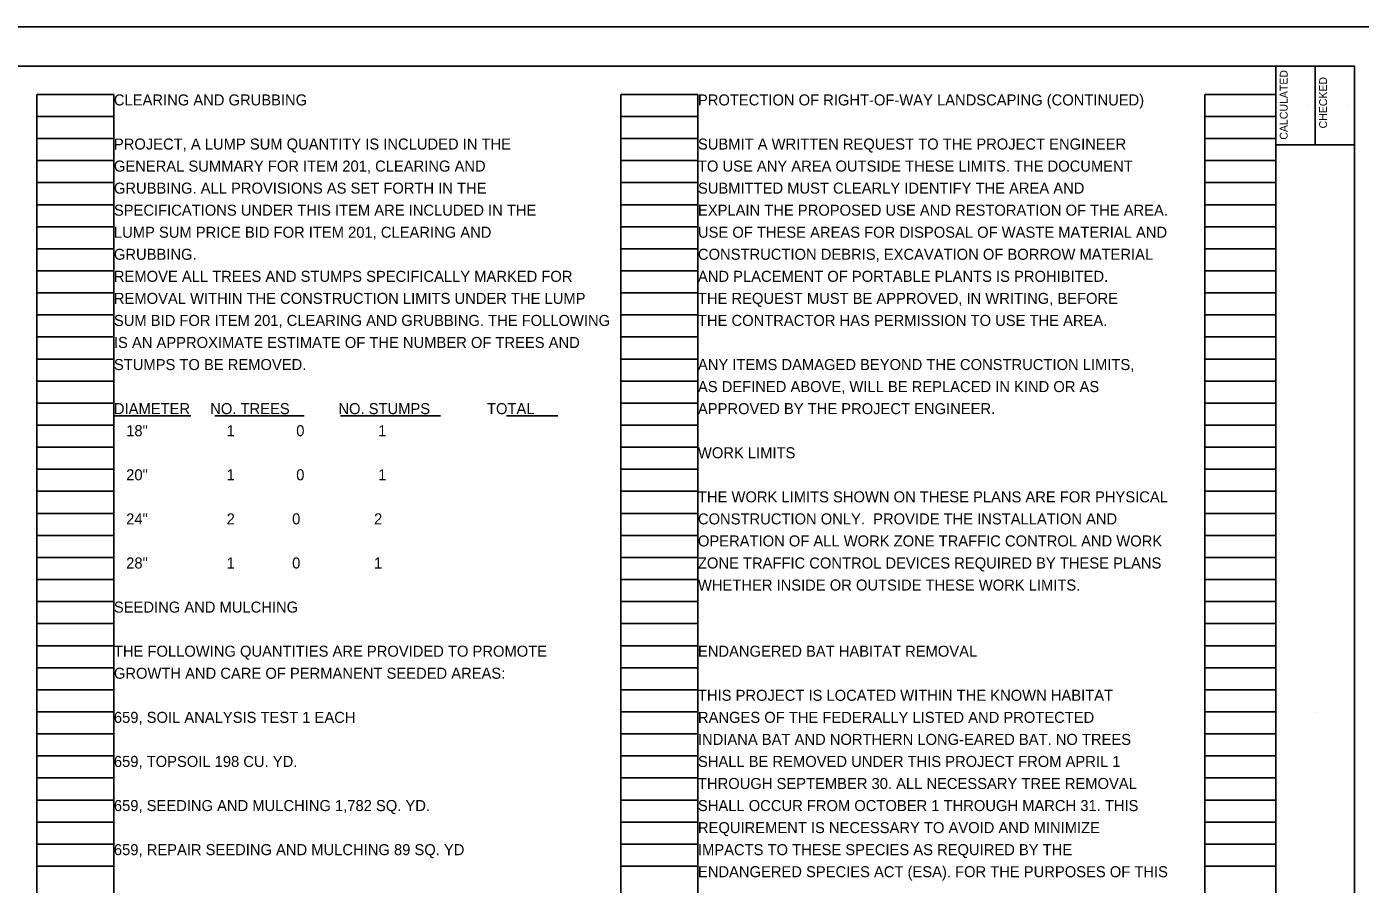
# Model space of a CAD drawing. Extents: x 0 to 50.5, y 0 to 22.
# Drawn here: x 16.63 to 33.58, y 11.11 to 22 of the extents above; entities that cross this region are included whole.
import ezdxf

# ---------------------------------------------------------------- set-up
doc = ezdxf.new("R2010")
doc.units = 0
for name, color, linetype in [('SC_Scratch1', 7, 'Continuous'), ('SH_Border', 7, 'Continuous'), ('SH_Cut_Line', 7, 'Continuous'), ('SH_Data', 7, 'Continuous'), ('SH_Text', 7, 'Continuous')]:
    doc.layers.add(name, color=color, linetype=linetype)

msp = doc.modelspace()

# ---------------------------------------------------------------- linework, layer by layer
at = {"layer": 'SC_Scratch1'}
for p, q in [((16.76, 0.98), (16.76, 21.14)), ((16.76, 21.14), (17.74, 21.14)), ((17.74, 0.98), (17.74, 21.14)), ((24.18, 0.98), (24.18, 21.14)), ((24.18, 21.14), (25.16, 21.14)), ((25.16, 0.98), (25.16, 21.14)), ((31.6, 0.98), (31.6, 21.14)), ((31.6, 21.14), (32.5, 21.14)), ((32.5, 0.98), (32.5, 21.14)), ((16.76, 20.86), (17.74, 20.86)), ((24.18, 20.86), (25.16, 20.86)), ((31.6, 20.86), (32.5, 20.86)), ((16.76, 20.58), (17.74, 20.58)), ((24.18, 20.58), (25.16, 20.58)), ((31.6, 20.58), (32.5, 20.58)), ((16.76, 20.3), (17.74, 20.3)), ((24.18, 20.3), (25.16, 20.3)), ((31.6, 20.3), (32.5, 20.3)), ((16.76, 20.02), (17.74, 20.02)), ((24.18, 20.02), (25.16, 20.02)), ((31.6, 20.02), (32.5, 20.02)), ((16.76, 19.74), (17.74, 19.74)), ((24.18, 19.74), (25.16, 19.74)), ((31.6, 19.74), (32.5, 19.74)), ((16.76, 19.46), (17.74, 19.46)), ((24.18, 19.46), (25.16, 19.46)), ((31.6, 19.46), (32.5, 19.46)), ((16.76, 19.18), (17.74, 19.18)), ((24.18, 19.18), (25.16, 19.18)), ((31.6, 19.18), (32.5, 19.18)), ((16.76, 18.9), (17.74, 18.9)), ((24.18, 18.9), (25.16, 18.9)), ((31.6, 18.9), (32.5, 18.9)), ((16.76, 18.62), (17.74, 18.62)), ((24.18, 18.62), (25.16, 18.62)), ((31.6, 18.62), (32.5, 18.62)), ((16.76, 18.34), (17.74, 18.34)), ((24.18, 18.34), (25.16, 18.34)), ((31.6, 18.34), (32.5, 18.34)), ((16.76, 18.06), (17.74, 18.06)), ((24.18, 18.06), (25.16, 18.06)), ((31.6, 18.06), (32.5, 18.06)), ((16.76, 17.78), (17.74, 17.78)), ((24.18, 17.78), (25.16, 17.78)), ((31.6, 17.78), (32.5, 17.78)), ((16.76, 17.5), (17.74, 17.5)), ((24.18, 17.5), (25.16, 17.5)), ((31.6, 17.5), (32.5, 17.5)), ((16.76, 17.22), (17.74, 17.22)), ((24.18, 17.22), (25.16, 17.22)), ((31.6, 17.22), (32.5, 17.22)), ((16.76, 16.94), (17.74, 16.94)), ((24.18, 16.94), (25.16, 16.94)), ((31.6, 16.94), (32.5, 16.94)), ((16.76, 16.66), (17.74, 16.66)), ((24.18, 16.66), (25.16, 16.66)), ((31.6, 16.66), (32.5, 16.66)), ((16.76, 16.38), (17.74, 16.38)), ((24.18, 16.38), (25.16, 16.38)), ((31.6, 16.38), (32.5, 16.38)), ((16.76, 16.1), (17.74, 16.1)), ((24.18, 16.1), (25.16, 16.1)), ((31.6, 16.1), (32.5, 16.1)), ((16.76, 15.82), (17.74, 15.82)), ((24.18, 15.82), (25.16, 15.82)), ((31.6, 15.82), (32.5, 15.82)), ((16.76, 15.54), (17.74, 15.54)), ((24.18, 15.54), (25.16, 15.54)), ((31.6, 15.54), (32.5, 15.54)), ((16.76, 15.26), (17.74, 15.26)), ((24.18, 15.26), (25.16, 15.26)), ((31.6, 15.26), (32.5, 15.26)), ((16.76, 14.98), (17.74, 14.98)), ((24.18, 14.98), (25.16, 14.98)), ((31.6, 14.98), (32.5, 14.98)), ((16.76, 14.7), (17.74, 14.7)), ((24.18, 14.7), (25.16, 14.7)), ((31.6, 14.7), (32.5, 14.7)), ((16.76, 14.42), (17.74, 14.42)), ((24.18, 14.42), (25.16, 14.42)), ((31.6, 14.42), (32.5, 14.42)), ((16.76, 14.14), (17.74, 14.14)), ((24.18, 14.14), (25.16, 14.14)), ((31.6, 14.14), (32.5, 14.14)), ((16.76, 13.86), (17.74, 13.86)), ((24.18, 13.86), (25.16, 13.86)), ((31.6, 13.86), (32.5, 13.86)), ((16.76, 13.58), (17.74, 13.58)), ((24.18, 13.58), (25.16, 13.58)), ((31.6, 13.58), (32.5, 13.58)), ((16.76, 13.3), (17.74, 13.3)), ((24.18, 13.3), (25.16, 13.3)), ((31.6, 13.3), (32.5, 13.3)), ((16.76, 13.02), (17.74, 13.02)), ((24.18, 13.02), (25.16, 13.02)), ((31.6, 13.02), (32.5, 13.02)), ((16.76, 12.74), (17.74, 12.74)), ((24.18, 12.74), (25.16, 12.74)), ((31.6, 12.74), (32.5, 12.74)), ((16.76, 12.46), (17.74, 12.46)), ((24.18, 12.46), (25.16, 12.46)), ((31.6, 12.46), (32.5, 12.46)), ((16.76, 12.18), (17.74, 12.18)), ((24.18, 12.18), (25.16, 12.18)), ((31.6, 12.18), (32.5, 12.18)), ((16.76, 11.9), (17.74, 11.9)), ((24.18, 11.9), (25.16, 11.9)), ((31.6, 11.9), (32.5, 11.9)), ((16.76, 11.62), (17.74, 11.62)), ((24.18, 11.62), (25.16, 11.62)), ((31.6, 11.62), (32.5, 11.62)), ((16.76, 11.34), (17.74, 11.34)), ((24.18, 11.34), (25.16, 11.34)), ((31.6, 11.34), (32.5, 11.34))]:
    msp.add_line(p, q, dxfattribs=at)
at = {"layer": 'SH_Border'}
for p, q in [((32.5, 0.5), (32.5, 21.5)), ((33, 21.5), (33, 20.5)), ((32.5, 20.5), (33.5, 20.5))]:
    msp.add_line(p, q, dxfattribs=at)
msp.add_lwpolyline([(2, 21.5), (33.5, 21.5), (33.5, 0.5), (2, 0.5)], close=True, dxfattribs=at)
at = {"layer": 'SH_Cut_Line'}
msp.add_lwpolyline([(0, 0), (34, 0), (34, 22), (0, 22)], close=True, dxfattribs=at)
at = {"layer": 'SH_Data'}
for p, q in [((32.92, 21.004), (32.92, 21.004)), ((33.42, 21.004), (33.42, 21.004)), ((33, 13.292), (33, 13.292))]:
    msp.add_line(p, q, dxfattribs=at)
at = {"layer": 'SH_Text'}
for p, q in [((17.737, 17.059), (18.717, 17.059)), ((19.023, 17.059), (20.158, 17.059)), ((20.617, 17.059), (21.888, 17.059)), ((22.727, 17.059), (23.38, 17.059))]:
    msp.add_line(p, q, dxfattribs=at)

# ---------------------------------------------------------------- texts
at = {"layer": 'SH_Data'}
for s, p in [('CALCULATED', (32.652, 20.565)), ('CHECKED', (33.152, 20.708))]:
    msp.add_text(s, height=0.1, rotation=90, dxfattribs=at).set_placement(p)
at = {"layer": 'SH_Text'}
for s, p in [('CLEARING AND GRUBBING', (17.74, 21)), ('PROTECTION OF RIGHT-OF-WAY LANDSCAPING (CONTINUED)', (25.16, 21)), ('PROJECT, A LUMP SUM QUANTITY IS INCLUDED IN THE', (17.74, 20.44)), ('SUBMIT A WRITTEN REQUEST TO THE PROJECT ENGINEER', (25.16, 20.44)), ('GENERAL SUMMARY FOR ITEM 201, CLEARING AND', (17.74, 20.16)), ('TO USE ANY AREA OUTSIDE THESE LIMITS. THE DOCUMENT', (25.16, 20.16)), ('GRUBBING. ALL PROVISIONS AS SET FORTH IN THE', (17.74, 19.88)), ('SUBMITTED MUST CLEARLY IDENTIFY THE AREA AND', (25.16, 19.88)), ('SPECIFICATIONS UNDER THIS ITEM ARE INCLUDED IN THE', (17.74, 19.6)), ('EXPLAIN THE PROPOSED USE AND RESTORATION OF THE AREA.', (25.16, 19.6)), ('LUMP SUM PRICE BID FOR ITEM 201, CLEARING AND', (17.74, 19.32)), ('USE OF THESE AREAS FOR DISPOSAL OF WASTE MATERIAL AND', (25.16, 19.32)), ('GRUBBING.', (17.74, 19.04)), ('CONSTRUCTION DEBRIS, EXCAVATION OF BORROW MATERIAL', (25.16, 19.04)), ('REMOVE ALL TREES AND STUMPS SPECIFICALLY MARKED FOR', (17.74, 18.76)), ('AND PLACEMENT OF PORTABLE PLANTS IS PROHIBITED.', (25.16, 18.76)), ('REMOVAL WITHIN THE CONSTRUCTION LIMITS UNDER THE LUMP', (17.74, 18.48)), ('THE REQUEST MUST BE APPROVED, IN WRITING, BEFORE', (25.16, 18.48)), ('SUM BID FOR ITEM 201, CLEARING AND GRUBBING. THE FOLLOWING', (17.74, 18.2)), ('THE CONTRACTOR HAS PERMISSION TO USE THE AREA.', (25.16, 18.2)), ('IS AN APPROXIMATE ESTIMATE OF THE NUMBER OF TREES AND', (17.74, 17.92)), ('STUMPS TO BE REMOVED.', (17.74, 17.64)), ('ANY ITEMS DAMAGED BEYOND THE CONSTRUCTION LIMITS,', (25.16, 17.64)), ('AS DEFINED ABOVE, WILL BE REPLACED IN KIND OR AS', (25.16, 17.36)), ('DIAMETER ', (17.74, 17.08)), ('  NO. TREES', (18.86, 17.08)), (' NO. STUMPS', (20.54, 17.08)), ('     TOTAL', (22.22, 17.08)), ('APPROVED BY THE PROJECT ENGINEER.', (25.16, 17.08)), ('   18"   ', (17.74, 16.8)), ('      1               0                  1', (18.86, 16.8)), ('WORK LIMITS', (25.16, 16.52)), ('   20"   ', (17.74, 16.24)), ('      1               0                  1', (18.86, 16.24)), ('THE WORK LIMITS SHOWN ON THESE PLANS ARE FOR PHYSICAL', (25.16, 15.96)), ('   24"   ', (17.74, 15.68)), ('      2              0                  2', (18.86, 15.68)), ('CONSTRUCTION ONLY.  PROVIDE THE INSTALLATION AND', (25.16, 15.68)), ('OPERATION OF ALL WORK ZONE TRAFFIC CONTROL AND WORK', (25.16, 15.4)), ('   28"   ', (17.74, 15.12)), ('      1              0                  1', (18.86, 15.12)), ('ZONE TRAFFIC CONTROL DEVICES REQUIRED BY THESE PLANS', (25.16, 15.12)), ('WHETHER INSIDE OR OUTSIDE THESE WORK LIMITS.', (25.16, 14.84)), ('SEEDING AND MULCHING', (17.74, 14.56)), ('THE FOLLOWING QUANTITIES ARE PROVIDED TO PROMOTE', (17.74, 14)), ('ENDANGERED BAT HABITAT REMOVAL', (25.16, 14)), ('GROWTH AND CARE OF PERMANENT SEEDED AREAS:', (17.74, 13.72)), ('THIS PROJECT IS LOCATED WITHIN THE KNOWN HABITAT', (25.16, 13.44)), ('659, SOIL ANALYSIS TEST 1 EACH', (17.74, 13.16)), ('RANGES OF THE FEDERALLY LISTED AND PROTECTED', (25.16, 13.16)), ('INDIANA BAT AND NORTHERN LONG-EARED BAT. NO TREES', (25.16, 12.88)), ('659, TOPSOIL 198 CU. YD.', (17.74, 12.6)), ('SHALL BE REMOVED UNDER THIS PROJECT FROM APRIL 1', (25.16, 12.6)), ('THROUGH SEPTEMBER 30. ALL NECESSARY TREE REMOVAL', (25.16, 12.32)), ('659, SEEDING AND MULCHING 1,782 SQ. YD.', (17.74, 12.04)), ('SHALL OCCUR FROM OCTOBER 1 THROUGH MARCH 31. THIS', (25.16, 12.04)), ('REQUIREMENT IS NECESSARY TO AVOID AND MINIMIZE', (25.16, 11.76)), ('659, REPAIR SEEDING AND MULCHING 89 SQ. YD', (17.74, 11.48)), ('IMPACTS TO THESE SPECIES AS REQUIRED BY THE', (25.16, 11.48)), ('ENDANGERED SPECIES ACT (ESA). FOR THE PURPOSES OF THIS', (25.16, 11.2))]:
    msp.add_text(s, height=0.14, dxfattribs=at).set_placement(p)

doc.saveas('drawing.dxf')
